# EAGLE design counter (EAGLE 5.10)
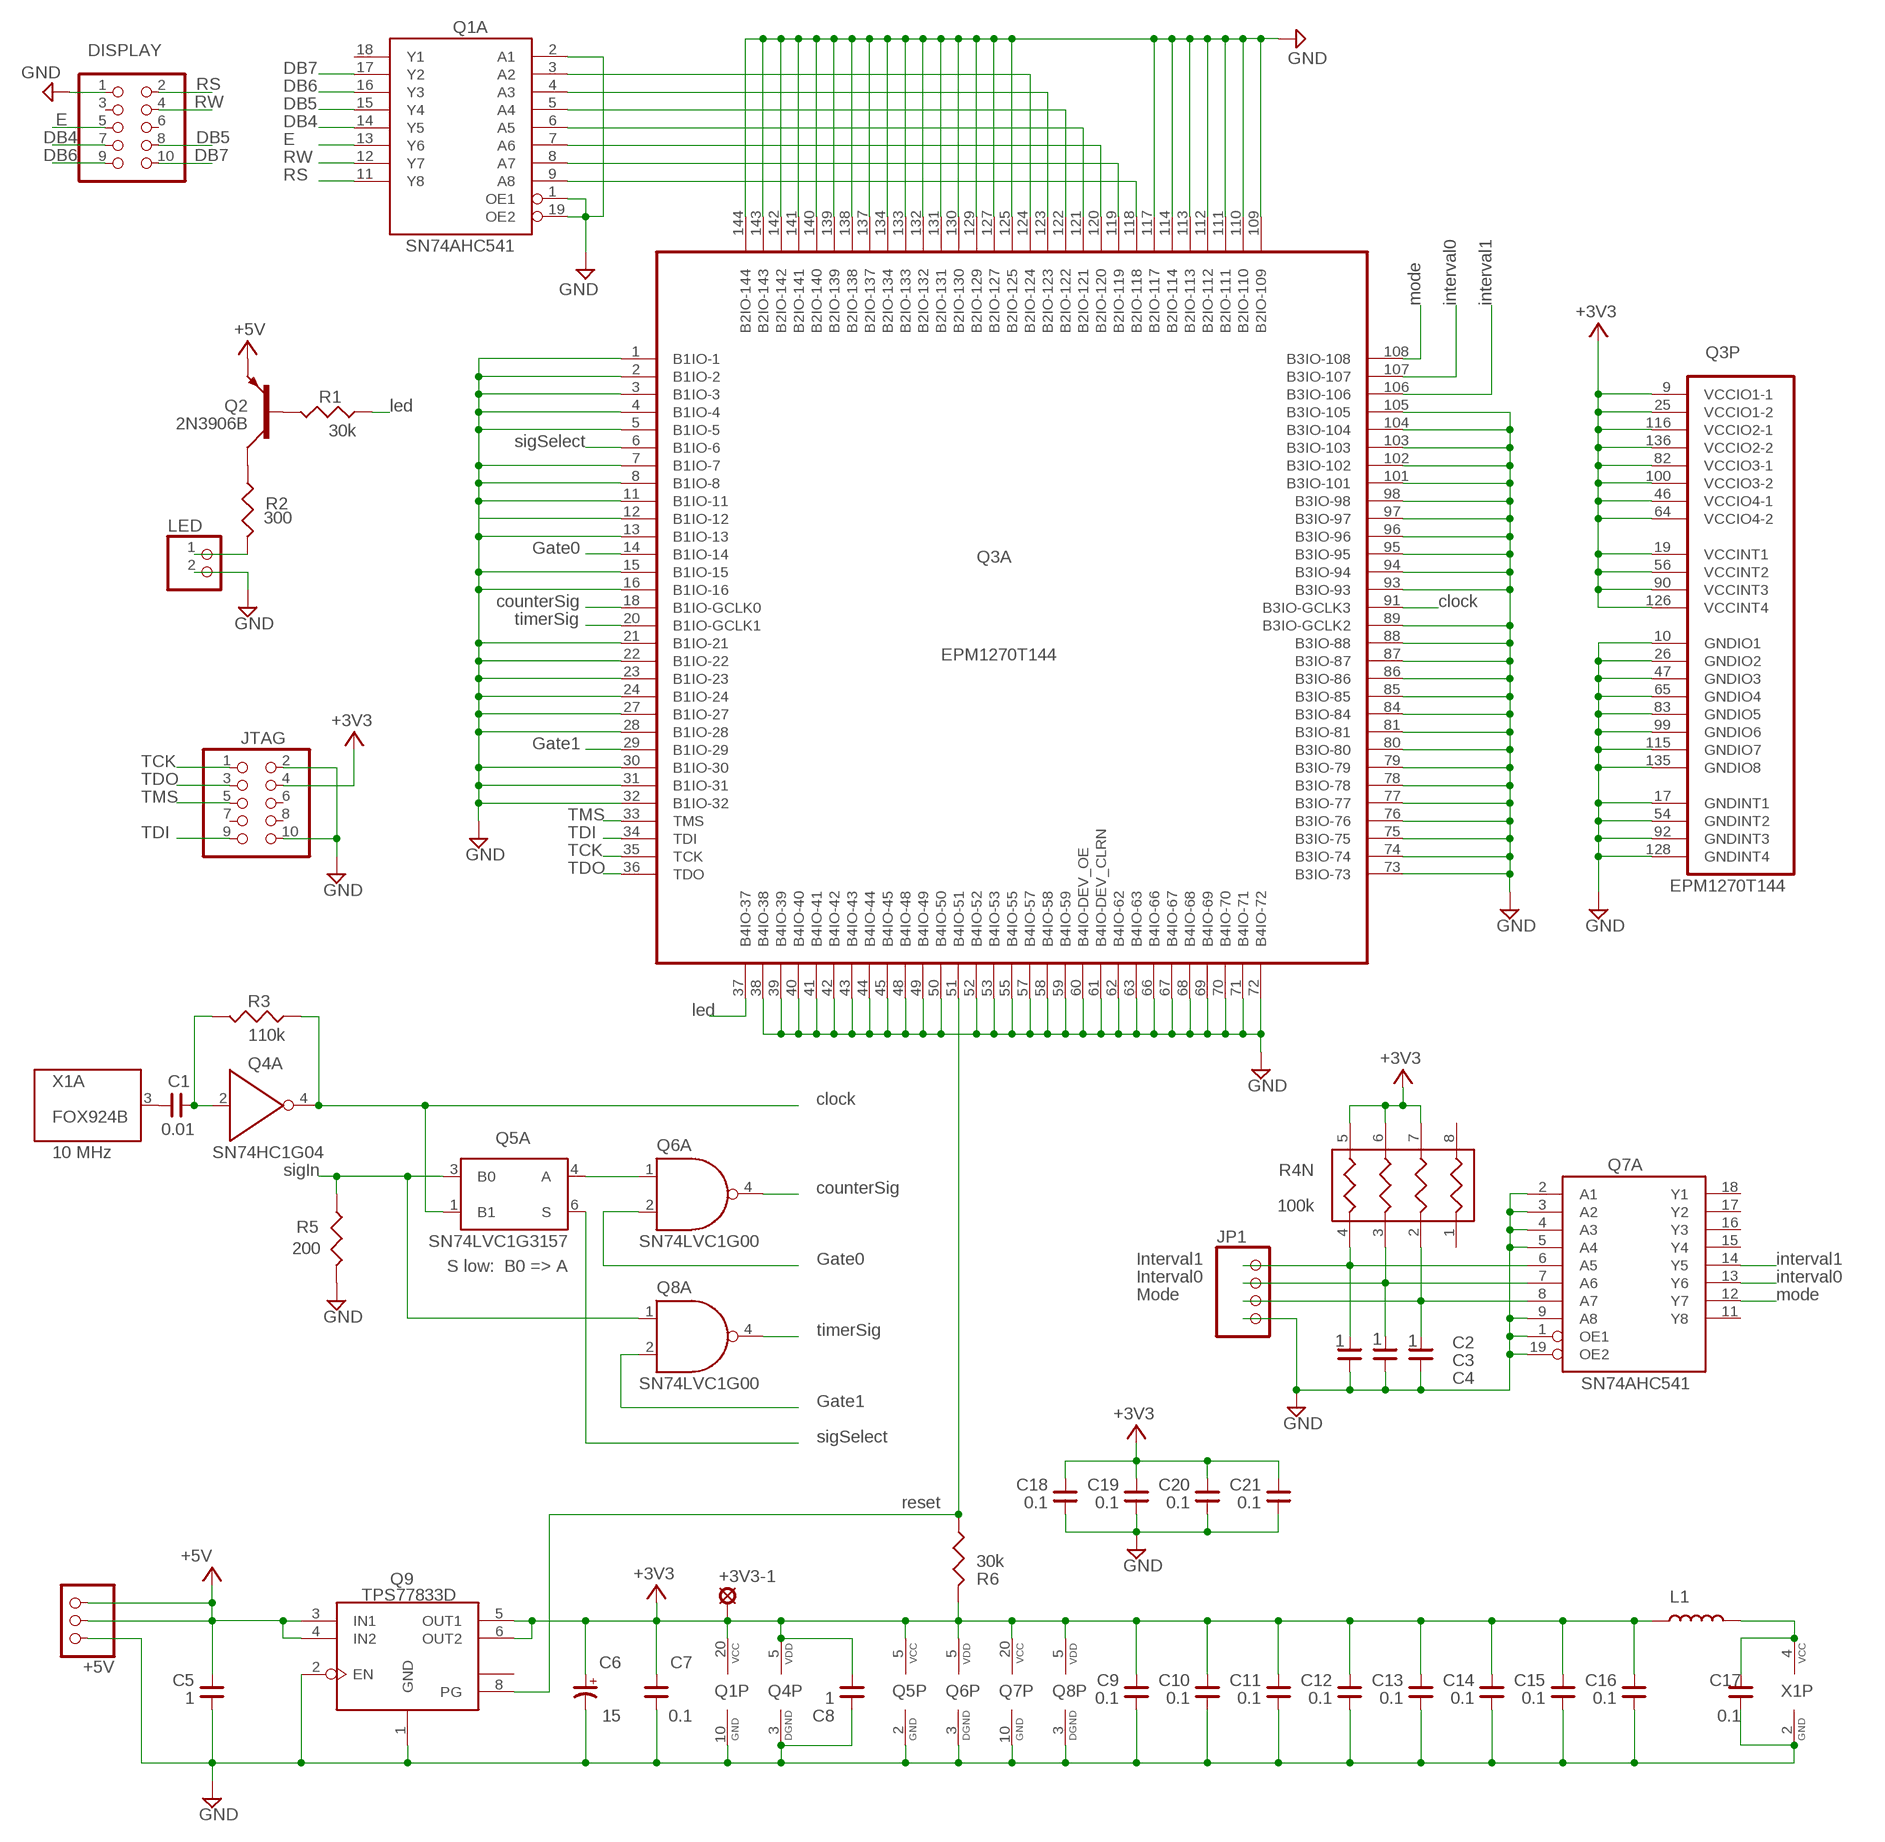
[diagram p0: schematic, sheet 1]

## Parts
+3V3-1  LSP10  [LSP10]
+5V  PINHD-1X3A  [1X03A]
C1  0.01  CAP-NPDC  [805C]
C2  1  CAP-NPDC  [805C]
C3  1  CAP-NPDC  [805C]
C4  1  CAP-NPDC  [805C]
C5  1  CAP-NPDC  [805C]
C6  15  CAP-PH  [BC45196H-B]
C7  0.1  CAP-NPDC  [805C]
C8  1  CAP-NPDC  [805C]
C9  0.1  CAP-NPDC  [805C]
C10  0.1  CAP-NPDC  [805C]
C11  0.1  CAP-NPDC  [805C]
C12  0.1  CAP-NPDC  [805C]
C13  0.1  CAP-NPDC  [805C]
C14  0.1  CAP-NPDC  [805C]
C15  0.1  CAP-NPDC  [805C]
C16  0.1  CAP-NPDC  [805C]
C17  0.1  CAP-NPDC  [805C]
C18  0.1  CAP-NPDC  [805C]
C19  0.1  CAP-NPDC  [805C]
C20  0.1  CAP-NPDC  [805C]
C21  0.1  CAP-NPDC  [805C]
DISPLAY  FOUR-WALL-2X5  [4W-2X5]
JP1  PINHD-1X4A  [1X4A-A]
JTAG  FOUR-WALL-2X5  [4W-2X5]
L1  INDUCTORC  [805A]
LED  PINHD-1X2  [1X02]
Q1  SN74AHC541  [TSSOP20]
Q2  2N3906B  [SOT23-3]
Q3  EPM1270T144  EPM1270T144-2  [TQFP144]
Q4  SN74HC1G04  1G04  [SOT-23-5]
Q5  SN74LVC1G3157  FSA3157A  [SOT-23-6]
Q6  SN74LVC1G00  1G00  [SOT23-5]
Q7  SN74AHC541  [TSSOP20]
Q8  SN74LVC1G00  1G00  [SOT23-5]
Q9  TPS77833D  [SOIC8]
R1  30k  RESISTORC  [805C]
R2  300  RESISTORC  [805C]
R3  110k  RESISTORC  [805C]
R4N  100k  RESISTOR-4-ARRAY  [1206-4-ARRAY]
R5  200  RESISTORC  [805C]
R6  30k  RESISTORC  [805C]
X1  FOX924B  OSC-NO-ENABLE  [FOX924]

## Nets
+3V3: +3V3-1.MP C6.+ C7.2 C8.2 C9.2 C10.2 C11.2 C12.2 C13.2 C14.2 C15.2 C16.2 C18.2 C19.2 C20.2 C21.2 JTAG.4 L1.1 Q1.20(P:VCC) Q3.9(P:VCCIO1-1) Q3.19(P:VCCINT1) Q3.25(P:VCCIO1-2) Q3.46(P:VCCIO4-1) Q3.56(P:VCCINT2) Q3.64(P:VCCIO4-2) Q3.82(P:VCCIO3-1) Q3.90(P:VCCINT3) Q3.100(P:VCCIO3-2) Q3.116(P:VCCIO2-1) Q3.126(P:VCCINT4) Q3.136(P:VCCIO2-2) Q4.5(P:VDD) Q5.5(P:VCC) Q6.5(P:VDD) Q7.20(P:VCC) Q8.5(P:VDD) Q9.5(OUT1) Q9.6(OUT2) R4N.5 R4N.6 R4N.7 R6.2
+5V: +5V.2 +5V.3 C5.2 Q2.2(E) Q9.3(IN1) Q9.4(IN2)
CLOCK: Q3.91(A:B3IO-GCLK3) Q4.4(A:Q) Q5.1(A:B1) R3.1
COUNTERSIG: Q3.18(A:B1IO-GCLK0) Q6.4(A:Y)
DB4: DISPLAY.7 Q1.14(A:Y5)
DB5: DISPLAY.8 Q1.15(A:Y4)
DB6: DISPLAY.9 Q1.16(A:Y3)
DB7: DISPLAY.10 Q1.17(A:Y2)
E: DISPLAY.5 Q1.13(A:Y6)
GATE0: Q3.14(A:B1IO-14) Q6.2(A:B)
GATE1: Q3.29(A:B1IO-29) Q8.2(A:B)
GND: +5V.1 C2.1 C3.1 C4.1 C5.1 C6.- C7.1 C8.1 C9.1 C10.1 C11.1 C12.1 C13.1 C14.1 C15.1 C16.1 C17.1 C18.1 C19.1 C20.1 C21.1 DISPLAY.1 JP1.4 JTAG.2 JTAG.10 LED.2 Q1.1(A:OE1) Q1.2(A:A1) Q1.10(P:GND) Q1.19(A:OE2) Q3.1(A:B1IO-1) Q3.2(A:B1IO-2) Q3.3(A:B1IO-3) Q3.4(A:B1IO-4) Q3.5(A:B1IO-5) Q3.7(A:B1IO-7) Q3.8(A:B1IO-8) Q3.10(P:GNDIO1) Q3.11(A:B1IO-11) Q3.12(A:B1IO-12) Q3.13(A:B1IO-13) Q3.15(A:B1IO-15) Q3.16(A:B1IO-16) Q3.17(P:GNDINT1) Q3.21(A:B1IO-21) Q3.22(A:B1IO-22) Q3.23(A:B1IO-23) Q3.24(A:B1IO-24) Q3.26(P:GNDIO2) Q3.27(A:B1IO-27) Q3.28(A:B1IO-28) Q3.30(A:B1IO-30) Q3.31(A:B1IO-31) Q3.32(A:B1IO-32) Q3.38(A:B4IO-38) Q3.39(A:B4IO-39) Q3.40(A:B4IO-40) Q3.41(A:B4IO-41) Q3.42(A:B4IO-42) Q3.43(A:B4IO-43) Q3.44(A:B4IO-44) Q3.45(A:B4IO-45) Q3.47(P:GNDIO3) Q3.48(A:B4IO-48) Q3.49(A:B4IO-49) Q3.50(A:B4IO-50) Q3.52(A:B4IO-52) Q3.53(A:B4IO-53) Q3.54(P:GNDINT2) Q3.55(A:B4IO-55) Q3.57(A:B4IO-57) Q3.58(A:B4IO-58) Q3.59(A:B4IO-59) Q3.60(A:B4IO-DEV_OE) Q3.61(A:B4IO-DEV_CLRN) Q3.62(A:B4IO-62) Q3.63(A:B4IO-63) Q3.65(P:GNDIO4) Q3.66(A:B4IO-66) Q3.67(A:B4IO-67) Q3.68(A:B4IO-68) Q3.69(A:B4IO-69) Q3.70(A:B4IO-70) Q3.71(A:B4IO-71) Q3.72(A:B4IO-72) Q3.73(A:B3IO-73) Q3.74(A:B3IO-74) Q3.75(A:B3IO-75) Q3.76(A:B3IO-76) Q3.77(A:B3IO-77) Q3.78(A:B3IO-78) Q3.79(A:B3IO-79) Q3.80(A:B3IO-80) Q3.81(A:B3IO-81) Q3.83(P:GNDIO5) Q3.84(A:B3IO-84) Q3.85(A:B3IO-85) Q3.86(A:B3IO-86) Q3.87(A:B3IO-87) Q3.88(A:B3IO-88) Q3.89(A:B3IO-GCLK2) Q3.92(P:GNDINT3) Q3.93(A:B3IO-93) Q3.94(A:B3IO-94) Q3.95(A:B3IO-95) Q3.96(A:B3IO-96) Q3.97(A:B3IO-97) Q3.98(A:B3IO-98) Q3.99(P:GNDIO6) Q3.101(A:B3IO-101) Q3.102(A:B3IO-102) Q3.103(A:B3IO-103) Q3.104(A:B3IO-104) Q3.105(A:B3IO-105) Q3.109(A:B2IO-109) Q3.110(A:B2IO-110) Q3.111(A:B2IO-111) Q3.112(A:B2IO-112) Q3.113(A:B2IO-113) Q3.114(A:B2IO-114) Q3.115(P:GNDIO7) Q3.117(A:B2IO-117) Q3.125(A:B2IO-125) Q3.127(A:B2IO-127) Q3.128(P:GNDINT4) Q3.129(A:B2IO-129) Q3.130(A:B2IO-130) Q3.131(A:B2IO-131) Q3.132(A:B2IO-132) Q3.133(A:B2IO-133) Q3.134(A:B2IO-134) Q3.135(P:GNDIO8) Q3.137(A:B2IO-137) Q3.138(A:B2IO-138) Q3.139(A:B2IO-139) Q3.140(A:B2IO-140) Q3.141(A:B2IO-141) Q3.142(A:B2IO-142) Q3.143(A:B2IO-143) Q3.144(A:B2IO-144) Q4.3(P:DGND) Q5.2(P:GND) Q6.3(P:DGND) Q7.1(A:OE1) Q7.2(A:A1) Q7.3(A:A2) Q7.4(A:A3) Q7.5(A:A4) Q7.9(A:A8) Q7.10(P:GND) Q7.19(A:OE2) Q8.3(P:DGND) Q9.1(GND) Q9.2(EN) R5.2 X1.2(P:GND)
INTERVAL0: Q3.107(A:B3IO-107) Q7.13(A:Y6)
INTERVAL0I: C3.2 JP1.2 Q7.7(A:A6) R4N.3
INTERVAL1: Q3.106(A:B3IO-106) Q7.14(A:Y5)
INTERVAL1I: C4.2 JP1.3 Q7.8(A:A7) R4N.2
LED: Q3.37(A:B4IO-37) R1.1
MODE: Q3.108(A:B3IO-108) Q7.12(A:Y7)
MODEI: C2.2 JP1.1 Q7.6(A:A5) R4N.4
N$1: Q1.3(A:A2) Q3.124(A:B2IO-124)
N$8: C1.2 X1.3(A:OUT)
N$13: C1.1 Q4.2(A:A) R3.2
N$14: Q1.4(A:A3) Q3.123(A:B2IO-123)
N$16: Q5.4(A:A) Q6.1(A:A)
N$17: Q1.5(A:A4) Q3.122(A:B2IO-122)
N$18: Q1.6(A:A5) Q3.121(A:B2IO-121)
N$19: Q1.7(A:A6) Q3.120(A:B2IO-120)
N$20: Q2.3(C) R2.1
N$21: LED.1 R2.2
N$22: Q1.8(A:A7) Q3.119(A:B2IO-119)
N$23: Q1.9(A:A8) Q3.118(A:B2IO-118)
N$25: Q2.1(B) R1.2
N$27: C17.2 L1.2 X1.4(P:VCC)
RESET: Q3.51(A:B4IO-51) Q9.8(PG) R6.1
RS: DISPLAY.2 Q1.11(A:Y8)
RW: DISPLAY.4 Q1.12(A:Y7)
SIGIN: Q5.3(A:B0) Q8.1(A:A) R5.1
SIGSELECT: Q3.6(A:B1IO-6) Q5.6(A:S)
TCK: JTAG.1 Q3.35(A:TCK)
TDI: JTAG.9 Q3.34(A:TDI)
TDO: JTAG.3 Q3.36(A:TDO)
TIMERSIG: Q3.20(A:B1IO-GCLK1) Q8.4(A:Y)
TMS: JTAG.5 Q3.33(A:TMS)
Unconnected: DISPLAY.3 DISPLAY.6 JTAG.6 JTAG.7 JTAG.8 Q1.18(A:Y1) Q7.11(A:Y8) Q7.15(A:Y4) Q7.16(A:Y3) Q7.17(A:Y2) Q7.18(A:Y1) Q9.7(NC) R4N.1 R4N.8

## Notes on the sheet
- DB7
- RS | DB6
- RW | DB5
- E | DB4
- DB4 | DB5 | E
- DB6 | DB7 | RW
- RS
- mode | interval0 | interval1
- led
- sigSelect
- Gate0
- counterSig | clock
- timerSig
- Gate1
- TCK
- TDO
- TMS
- TMS
- TDI | TDI
- TCK
- TDO
- led
- clock
- 10 MHz
- sigIn
- counterSig
- Gate0 | Interval1 | interval1
- S low:  B0 => A
- Interval0 | interval0
- Mode | mode
- timerSig
- Gate1
- sigSelect
- reset

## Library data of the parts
+3V3-1 = agar2:LSP10: SOLDER PAD
+5V = agarConn:PINHD-1X3
C1-C5 C7-C21 = agar:CAP-NP: Non-polarized capacitor
C6 = agar:CAP-P: Polarized capacitor
DISPLAY JTAG = agarConn:FOUR-WALL-2X5
JP1 = agarConn:PINHD-1X4
L1 = agar:INDUCTOR: Fixed inductor
LED = agarConn:PINHD-1X2: PIN HEADER
Q1 Q7 = agarDigital:SN74AHC541: Octal buffer/driver with 3-state outputs
Q2 = agar:2N3906: PNP TRANSISTOR
Q3 = epm1270t144:EPM1270T144-2: EMP1270T144
Q4 = agarDigital:1G04: NOT
Q5 = agarDigital:FSA3157: Low-voltage SPDT analog switch
Q6 Q8 = agarDigital:1G00: Single positive-nand gate
Q9 = agarVoltageReg:TPS77833D: LDO reg with power-good output.
R1-R3 R5 R6 = agar:RESISTOR
R4N = agar:RESISTOR-4-ARRAY
X1 = agar:OSC-NO-ENABLE

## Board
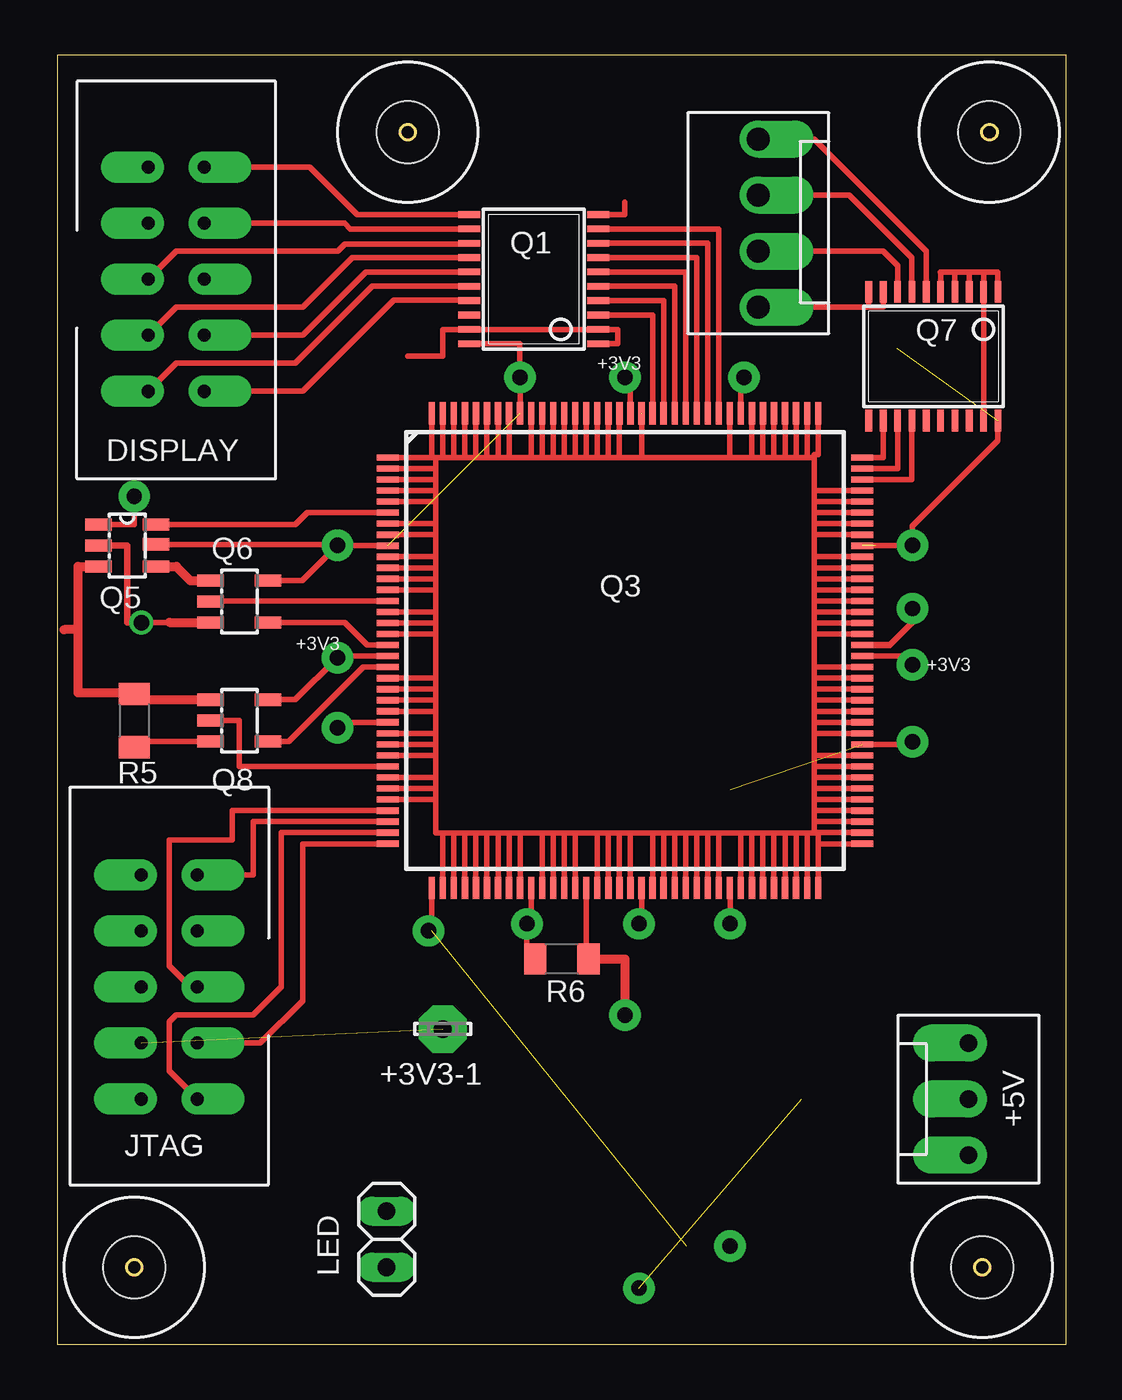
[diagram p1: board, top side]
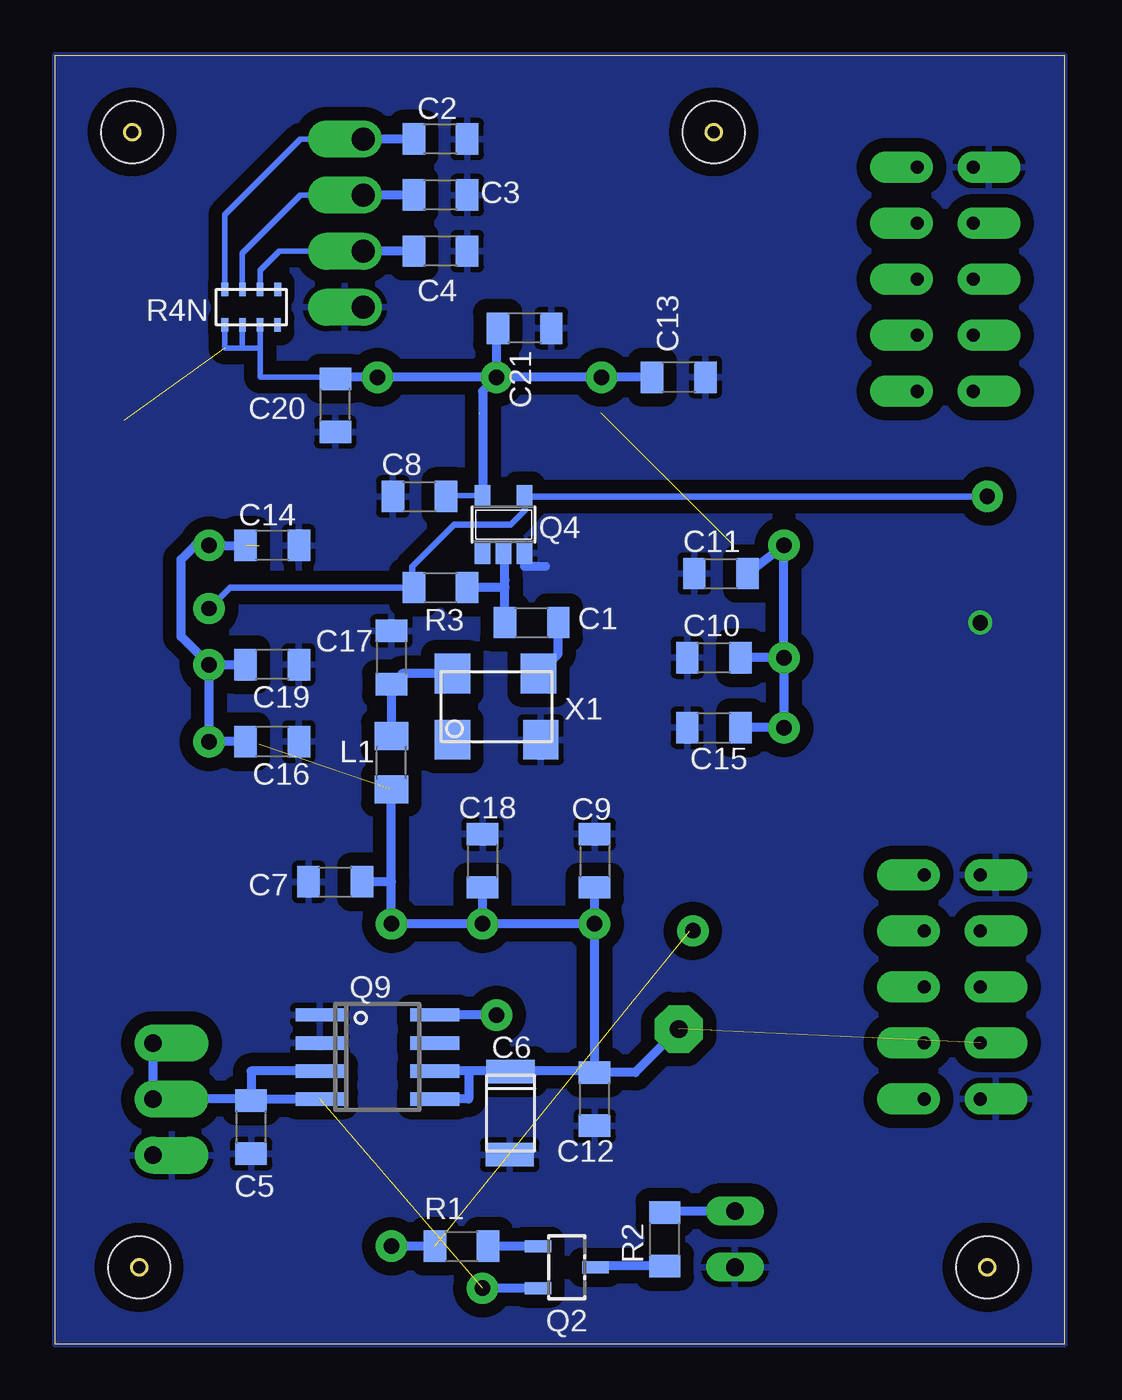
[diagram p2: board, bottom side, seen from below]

Size 45.71 x 58.41 mm. Coordinates in mm from the lower left corner, seen from the top.
Outline: 0,0 45.71,0 45.71,58.41 0,58.41 0,0
Copper layers (1*16): Top 0.035mm / dielectric 1.5mm / Bottom 0.035mm
Design rules "default *": minimum track width 10mil, minimum drill 24mil, track to track 8mil, track to pad 8mil, pad to pad 8mil, via to via 8mil, smd to smd 8mil, copper to edge 0mil, drill to drill 8mil, minimum pad ring 10mil, minimum via ring 8mil, stop-mask expansion 4mil, vias tented up to drill 0mil, thermal gap 10mil

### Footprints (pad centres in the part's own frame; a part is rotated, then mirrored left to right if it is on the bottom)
LSP10 = drill 0.8 pad 2.159 octagon: MP 0,0
1X03A = drill 0.8 pad 1.676 offset: 1 0,2.54; 2 0,0; 3 0,-2.54
805C = smd 1.016 x 1.422: 1 -1.206,0; 2 1.206,0
BC45196H-B = smd 1.067 x 2.184: + -1.883,0; - 1.883,-0.038
4W-2X5 = drill 0.6 pad 1.422 offset: 1 -5.08,-1.27; 2 -5.08,1.27; 3 -2.54,-1.27; 4 -2.54,1.27; 5 0,-1.27; 6 0,1.27; 7 2.54,-1.27; 8 2.54,1.27; 9 5.08,-1.27; 10 5.08,1.27
1X4A-A = drill 1.041 pad 1.676 offset: 1 0,3.81; 2 0,1.27; 3 0,-1.27; 4 0,-3.81
805A = smd 1.27 x 1.524: 1 -1.206,0; 2 1.206,0
1X02 = drill 0.8 long: 1 -1.27,0; 2 1.27,0
TSSOP20 = smd 0.305 x 0.991: 1 -2.925,-2.918; 2 -2.275,-2.918; 3 -1.625,-2.918; 4 -0.975,-2.918; 5 -0.325,-2.918; 6 0.325,-2.918; 7 0.975,-2.918; 8 1.625,-2.918; 9 2.275,-2.918; 10 2.925,-2.918; 11 2.925,2.918; 12 2.275,2.918; 13 1.625,2.918; 14 0.975,2.918; 15 0.325,2.918; 16 -0.325,2.918; 17 -0.975,2.918; 18 -1.625,2.918; 19 -2.275,2.918; 20 -2.925,2.918
SOT23-3 = smd 0.55 x 1.2: 1 0.95,1.3; 2 -0.95,1.3; 3 0,-1.3
TQFP144 = smd 1 x 0.279: 1 -10.75,8.75 | smd 1 x 0.282: 2 -10.75,8.25; 3 -10.75,7.75; 4 -10.75,7.25; 5 -10.75,6.75; 6 -10.75,6.25; 7 -10.75,5.75; 8 -10.75,5.25; 9 -10.75,4.75; 10 -10.75,4.25; 11 -10.75,3.75; 12 -10.75,3.25; 13 -10.75,2.75; 14 -10.75,2.25; 15 -10.75,1.75; 16 -10.75,1.25; 17 -10.75,0.75; 18 -10.75,0.25; 19 -10.75,-0.25; 20 -10.75,-0.75; 21 -10.75,-1.25; 22 -10.75,-1.75; 23 -10.75,-2.25; 24 -10.75,-2.75; 25 -10.75,-3.25; 26 -10.75,-3.75; 27 -10.75,-4.25; 28 -10.75,-4.75; 29 -10.75,-5.25; 30 -10.75,-5.75; 31 -10.75,-6.25; 32 -10.75,-6.75; 33 -10.75,-7.25; 34 -10.75,-7.75; 35 -10.75,-8.25; 36 -10.75,-8.75; 73 10.75,-8.75; 74 10.75,-8.25; 75 10.75,-7.75; 76 10.75,-7.25; 77 10.75,-6.75; 78 10.75,-6.25; 79 10.75,-5.75; 80 10.75,-5.25; 81 10.75,-4.75; 82 10.75,-4.25; 83 10.75,-3.75; 84 10.75,-3.25; 85 10.75,-2.75; 86 10.75,-2.25; 87 10.75,-1.75; 88 10.75,-1.25; 89 10.75,-0.75; 90 10.75,-0.25; 91 10.75,0.25; 92 10.75,0.75; 93 10.75,1.25; 94 10.75,1.75; 95 10.75,2.25; 96 10.75,2.75; 97 10.75,3.25; 98 10.75,3.75; 99 10.75,4.25; 100 10.75,4.75; 101 10.75,5.25; 102 10.75,5.75; 103 10.75,6.25; 104 10.75,6.75; 105 10.75,7.25; 106 10.75,7.75; 107 10.75,8.25; 108 10.75,8.75 | smd 0.282 x 1: 37 -8.75,-10.75; 38 -8.25,-10.75; 39 -7.75,-10.75; 40 -7.25,-10.75; 41 -6.75,-10.75; 42 -6.25,-10.75; 43 -5.75,-10.75; 44 -5.25,-10.75; 46 -4.25,-10.75; 47 -3.75,-10.75; 48 -3.25,-10.75; 49 -2.75,-10.75; 50 -2.25,-10.75; 51 -1.75,-10.75; 52 -1.25,-10.75; 53 -0.75,-10.75; 54 -0.25,-10.75; 55 0.25,-10.75; 56 0.75,-10.75; 57 1.25,-10.75; 58 1.75,-10.75; 59 2.25,-10.75; 60 2.75,-10.75; 61 3.25,-10.75; 62 3.75,-10.75; 63 4.25,-10.75; 64 4.75,-10.75; 65 5.25,-10.75; 66 5.75,-10.75; 67 6.25,-10.75; 68 6.75,-10.75; 69 7.25,-10.75; 70 7.75,-10.75; 71 8.25,-10.75; 72 8.75,-10.75; 109 8.75,10.75; 110 8.25,10.75; 111 7.75,10.75; 112 7.25,10.75; 113 6.75,10.75; 114 6.25,10.75; 115 5.75,10.75; 116 5.25,10.75; 117 4.75,10.75; 118 4.25,10.75; 119 3.75,10.75; 120 3.25,10.75; 121 2.75,10.75; 122 2.25,10.75; 123 1.75,10.75; 124 1.25,10.75; 125 0.75,10.75; 126 0.25,10.75; 127 -0.25,10.75; 128 -0.75,10.75; 129 -1.25,10.75; 130 -1.75,10.75; 131 -2.25,10.75; 132 -2.75,10.75; 133 -3.25,10.75; 134 -3.75,10.75; 135 -4.25,10.75; 136 -4.75,10.75; 137 -5.25,10.75; 138 -5.75,10.75; 139 -6.25,10.75; 140 -6.75,10.75; 141 -7.25,10.75; 142 -7.75,10.75; 143 -8.25,10.75; 144 -8.75,10.75 | smd 0.3 x 1: 45 -4.75,-10.75
SOT-23-5 = smd 0.69 x 0.99: 1 -0.95,-1.29; 2 0,-1.29; 3 0.95,-1.29; 4 0.95,1.3; 5 -0.95,1.3
SOT-23-6 = smd 0.55 x 1.2: 1 -0.95,-1.3; 2 0,-1.3; 3 0.95,-1.3; 4 0.95,1.3; 5 -0.05,1.3; 6 -0.95,1.3
SOT23-5 = smd 0.55 x 1.2: 1 -0.95,-1.3; 2 0,-1.3; 3 0.95,-1.3; 4 0.95,1.3; 5 -0.95,1.3
SOIC8 = smd 0.6 x 2.2: 1 -1.905,-2.6; 2 -0.635,-2.6; 3 0.635,-2.6; 4 1.905,-2.6; 5 1.905,2.6; 6 0.635,2.6; 7 -0.635,2.6; 8 -1.905,2.6
1206-4-ARRAY = smd 0.305 x 0.61: 1 -1.2,-0.8; 2 -0.4,-0.8; 3 0.4,-0.8; 4 1.2,-0.8; 5 1.2,0.8; 6 0.4,0.8; 7 -0.4,0.8; 8 -1.194,0.808
MOUNTING-HOLE-PLAIN = hole 2.8: 0,0
FOX924 = smd 1.6 x 1.8: 1 -2,-1.5; 2 2,-1.5; 3 1.9,1.5; 4 -2,1.5

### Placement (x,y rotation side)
+3V3-1  17.46,14.29 0 top
+5V  41.27,11.11 180 top
C1  24.13,32.7 0 bottom
C2  28.26,54.61 180 bottom
C3  28.26,52.07 180 bottom
C4  28.26,49.53 180 bottom
C5  36.83,9.84 90 bottom
C6  25.08,10.48 270 bottom
C7  33.02,20.95 0 bottom
C8  29.21,38.42 0 bottom
C9  21.27,21.91 270 bottom
C10  15.88,31.11 0 bottom
C11  15.56,34.92 0 bottom
C12  21.27,11.11 90 bottom
C13  17.46,43.81 180 bottom
C14  35.88,36.2 180 bottom
C15  15.88,27.94 0 bottom
C16  35.88,27.3 180 bottom
C17  30.48,31.11 270 bottom
C18  26.35,21.91 270 bottom
C19  35.88,30.8 180 bottom
C20  33.02,42.55 90 bottom
C21  24.45,46.04 180 bottom
DISPLAY  5.4,48.26 270 top
JP1  31.75,50.8 0 top
JTAG  5.08,16.19 90 top
L1  30.48,26.35 90 bottom
LED  14.92,4.76 270 top
Q1  21.59,48.26 90 top
Q2  22.54,3.49 90 bottom
Q3  25.72,31.43 0 top
Q4  25.4,37.15 0 bottom
Q5  3.17,36.2 270 top
Q6  8.26,33.66 270 top
Q7  39.69,44.77 180 top
Q8  8.26,28.26 270 top
Q9  31.11,13.02 270 bottom
R1  27.3,4.45 0 bottom
R2  18.1,4.76 90 bottom
R3  28.26,34.29 0 bottom
R4N  36.83,46.99 180 bottom
R5  3.49,28.26 270 top
R6  22.86,17.46 180 top
U$1  [MOUNTING-HOLE-PLAIN]  3.49,3.49 0 top
U$2  [MOUNTING-HOLE-PLAIN]  41.91,3.49 0 top
U$3  [MOUNTING-HOLE-PLAIN]  42.23,54.93 0 top
U$4  [MOUNTING-HOLE-PLAIN]  15.88,54.93 0 top
X1  25.72,28.89 0 bottom

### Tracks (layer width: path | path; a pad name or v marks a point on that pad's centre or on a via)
+3V3  (via drill 0.7 pad 1.42)  (5 unrouted)
  Top 0.254: Q6.5 11.11,34.6 12.69,36.18 12.71,36.18 | 12.71,36.18 Q3.9 | 12.71,36.18 v12.7,36.2 12.65,36.24 Q5.5 | Q3.19 12.77,31.18 v12.7,31.11 10.79,29.21 Q8.5 | Q3.90 38.48,31.18 v38.73,30.8 | Q3.136 20.97,43.8 v20.95,43.81 20.95,45.34 Q1.20 | Q3.126 25.97,43.56 v25.72,43.81 | Q3.116 30.97,43.67 v31.11,43.81 | v30.48,19.05 Q3.64 | Q3.56 26.47,19.16 v26.35,19.05 | Q3.46 21.47,19.25 v21.27,19.05 21.27,17.46 R6.2 | Q3.25 12.94,28.18 v12.7,27.94 | Q7.20 42.61,40.96 38.73,37.08 v38.73,36.2 38.72,36.18 Q3.100 | Q3.82 38.61,27.18 v38.73,27.3
  Bottom 0.254: Q4.5 27.97,38.45 C8.2 | L1.1 30.42,25.08 | 33.02,43.81 36.43,43.81 36.43,45.14 | 36.43,45.14 R4N.7 | 36.43,45.14 37.23,45.14 | R4N.5 38.03,45.14 37.23,45.14 | 37.23,45.14 R4N.6
  Bottom 0.406: Q4.5 26.35,43.18 v25.72,43.81 | 30.48,20.95 v30.48,19.05 v26.35,19.05 | 30.48,20.95 L1.1 | v21.27,19.05 v26.35,19.05 | v38.73,30.8 v38.73,27.3 C16.2 | v38.73,30.8 40.01,32.07 40.01,35.56 39.37,36.2 C14.2 | v25.72,43.81 v20.95,43.81 C13.2 | v12.7,31.11 v12.7,36.2 C11.2 | v12.7,31.11 v12.7,27.94 C15.2 | v12.7,31.11 C10.2 | v21.27,19.05 C9.2 | v38.73,30.8 C19.2 | v26.35,19.05 C18.2 | 30.48,20.95 C7.2 | 25.08,12.38 26.99,12.38 | 26.99,12.38 Q9.6 | 25.08,12.38 C6.+ | Q9.5 26.99,11.11 26.99,12.38 | 25.08,12.38 21.91,12.38 C12.2 | C12.2 v21.27,19.05 | C12.2 19.43,12.32 +3V3-1.MP | C21.2 25.72,46.04 v25.72,43.81 | v25.72,43.81 v31.11,43.81 33.02,43.81 C20.2
+5V  (via drill 0.7 pad 1.42)  (1 unrouted)
  Bottom 0.406: +5V.3 +5V.2 36.83,11.11 | 36.83,11.11 Q9.4 | 36.83,11.11 C5.2 36.83,12.38 Q9.3 | Q2.2 v26.35,2.54
CLOCK  (via drill 0.7 pad 1.42)
  Top 0.254: Q5.1 3.49,37.15 v3.49,38.42
  Top 0.305: Q3.91 37.72,31.68 38.73,32.7 v38.73,33.34
  Bottom 0.254: v3.49,38.42 3.49,38.35 | 29.53,34.35 R3.1 | 24.45,38.42 Q4.4
  Bottom 0.305: Q4.4 24.45,37.78 25.08,37.15 27.62,37.15 29.53,35.24 29.53,34.35 | v3.49,38.42 24.45,38.42 | R3.1 37.78,34.29 v38.73,33.34
COUNTERSIG
  Top 0.254: Q3.18 14.04,31.68 13.02,32.7 Q6.4
DB4
  Top 0.254: Q1.14 13.36,49.23 11.11,46.99 5.4,46.99 DISPLAY.7
DB5
  Top 0.254: Q1.15 18.66,48.58 13.97,48.58 11.11,45.72 DISPLAY.8
DB6
  Top 0.254: Q1.16 14.28,47.94 10.79,44.45 5.4,44.45 DISPLAY.9
DB7
  Top 0.254: Q1.17 18.65,47.31 15.24,47.31 11.11,43.18 DISPLAY.10
E
  Top 0.254: Q1.13 18.64,49.85 13.02,49.85 12.7,49.53 5.4,49.53 DISPLAY.5
GATE0
  Top 0.254: Q3.14 6.96,33.68 Q6.2
GATE1
  Top 0.254: Q8.2 8.26,28.26 8.26,26.18 Q3.29
GND  (via drill 0.7)  (1 unrouted)
  Top 0.254: v3.81,32.7 5.08,32.7 | Q8.3 3.75,27.31 R5.2 | 15.88,44.77 17.46,44.77 17.46,45.98 Q1.19 Q1.2 25.4,45.98 25.4,45.34 Q1.1 | 17.14,40.18 16.97,40.18 | 17.14,26.68 17.14,27.18 | 17.14,24.68 17.14,23.18 17.46,23.18 | 17.14,39.68 17.14,40.18 | 18.47,23.18 18.97,23.18 | 19.47,23.18 19.97,23.18 | 21.97,23.18 22.47,23.18 | 22.97,23.18 23.47,23.18 | 24.47,23.18 24.97,23.18 | 25.47,23.18 25.97,23.18 | 32.47,23.18 32.97,23.18 | 31.47,23.18 31.97,23.18 | 28.97,23.18 29.47,23.18 | 27.97,23.18 28.47,23.18 | 18.47,40.18 18.97,40.18 | 19.97,40.18 20.47,40.18 | 22.47,40.18 22.97,40.18 | 24.97,40.18 25.47,40.18 | 34.29,38.68 34.29,38.18 | 34.29,37.68 34.29,37.18 | 34.29,33.68 34.29,34.18 | 34.29,32.18 34.29,32.68 | 34.29,30.18 34.29,30.68 | 34.29,28.68 34.29,29.18 | 34.29,27.68 34.29,28.18 | 34.29,25.18 34.29,25.68 | 34.29,23.18 34.29,23.68 | 17.14,39.68 Q3.2 | 17.14,39.18 17.14,39.68 | 17.14,39.18 Q3.3 | 17.14,38.68 17.14,39.18 | 17.14,38.68 Q3.4 | 17.14,38.18 17.14,38.68 | 17.14,38.18 Q3.5 | 17.14,37.18 17.14,38.18 | 17.14,37.18 Q3.7 | 17.14,36.68 17.14,37.18 | 17.14,36.68 Q3.8 | 17.14,33.18 Q3.15 | 17.14,32.68 17.14,33.18 | 17.14,32.68 Q3.16 | 17.14,32.18 17.14,32.68 | 17.14,32.18 Q3.17 | 17.14,30.18 17.14,32.18 | 17.14,30.18 Q3.21 | 17.14,29.68 17.14,30.18 | 17.14,29.68 Q3.22 | 17.14,29.18 17.14,29.68 | 17.14,29.18 Q3.23 | 17.14,28.68 17.14,29.18 | 17.14,28.68 Q3.24 | 17.14,27.68 17.14,28.68 | 17.14,27.68 Q3.26 | 17.14,27.18 Q3.27 | 17.14,27.18 17.14,27.68 | 17.14,26.68 Q3.28 | 17.14,25.68 Q3.30 | 17.14,25.68 17.14,26.68 | Q3.31 17.14,25.18 | 17.14,25.18 17.14,25.68 | 17.14,24.68 Q3.32 | 17.14,25.18 17.14,24.68 | Q3.38 17.46,23.18 | 17.46,23.18 17.97,23.18 | 17.97,23.18 Q3.39 | 17.97,23.18 18.47,23.18
  Top 0.254: 18.47,23.18 Q3.40 | 18.97,23.18 Q3.41 | 18.97,23.18 19.47,23.18 | 19.47,23.18 Q3.42 | 19.97,23.18 Q3.43 | 19.97,23.18 20.47,23.18 | 20.47,23.18 Q3.44 | 20.47,23.18 20.97,23.18 | 20.97,23.18 Q3.45 | 20.97,23.18 21.97,23.18 | 21.97,23.18 Q3.47 | 22.47,23.18 Q3.48 | 22.47,23.18 22.97,23.18 | 22.97,23.18 Q3.49 | 23.47,23.18 Q3.50 | 23.47,23.18 24.47,23.18 | 24.47,23.18 Q3.52 | 24.97,23.18 Q3.53 | 24.97,23.18 25.47,23.18 | 25.47,23.18 Q3.54 | 25.97,23.18 26.97,23.18 | 25.97,23.18 Q3.55 | 26.97,23.18 27.47,23.18 | 26.97,23.18 Q3.57 | 27.47,23.18 Q3.58 | 27.47,23.18 27.97,23.18 | 27.97,23.18 Q3.59 | 28.47,23.18 Q3.60 | 28.47,23.18 28.97,23.18 | 28.97,23.18 Q3.61 | 29.47,23.18 Q3.62 | 29.47,23.18 29.97,23.18 | 29.97,23.18 Q3.63 | 29.97,23.18 30.97,23.18 | 30.97,23.18 Q3.65 | 30.97,23.18 31.47,23.18 | 31.47,23.18 Q3.66 | 31.97,23.18 Q3.67 | 31.97,23.18 32.47,23.18 | 32.47,23.18 Q3.68 | 32.97,23.18 33.47,23.18 | 32.97,23.18 Q3.69 | 33.47,23.18 33.97,23.18 | 33.47,23.18 Q3.70 | 33.97,23.18 34.29,23.18 | 33.97,23.18 Q3.71 | 34.29,23.18 34.47,23.18 | 34.47,23.18 34.47,22.68 | Q3.74 34.47,23.18 | 34.47,22.68 Q3.73 | 34.47,22.68 Q3.72 | 34.29,23.68 Q3.75 | 34.29,24.18 Q3.76 | 34.29,23.68 34.29,24.18 | 34.29,24.68 Q3.77 | 34.29,24.18 34.29,24.68 | 34.29,25.18 Q3.78 | 34.29,24.68 34.29,25.18 | 34.29,25.68 Q3.79 | 34.29,26.18 Q3.80 | 34.29,25.68 34.29,26.18 | 34.29,26.68 Q3.81 | 34.29,26.18 34.29,26.68 | 34.29,27.68 Q3.83 | 34.29,26.68 34.29,27.68 | 34.29,28.18 Q3.84 | 34.29,28.68 Q3.85 | 34.29,28.18 34.29,28.68 | 34.29,29.18 Q3.86 | 34.29,29.18 34.29,29.68 | 34.29,29.68 Q3.87 | 34.29,30.18 Q3.88 | 34.29,29.68 34.29,30.18 | 34.29,30.68 Q3.89 | 34.29,32.18 Q3.92 | 34.29,30.68 34.29,32.18 | 34.29,32.68 Q3.93 | 34.29,32.68 34.29,33.18
  Top 0.254: 34.29,33.18 Q3.94 | 34.29,33.68 Q3.95 | 34.29,33.18 34.29,33.68 | 34.29,34.18 Q3.96 | 34.29,34.18 34.29,34.68 | 34.29,34.68 Q3.97 | 34.29,34.68 34.29,35.18 | 34.29,35.18 Q3.98 | 34.29,35.68 Q3.99 | 34.29,35.68 34.29,35.18 | 34.29,36.68 Q3.101 | 34.29,36.68 34.29,35.68 | 34.29,37.18 Q3.102 | 34.29,37.18 34.29,36.68 | 34.29,37.68 Q3.103 | 34.29,38.18 Q3.104 | 34.29,38.18 34.29,37.68 | 34.29,38.68 Q3.105 | 34.29,40.18 34.29,38.68 | 34.29,40.18 34.29,40.32 34.47,40.32 Q3.109 | 33.97,40.18 34.29,40.18 | 33.97,40.18 Q3.110 | 32.97,40.18 33.47,40.18 | 32.97,40.18 Q3.112 | 32.47,40.18 32.97,40.18 | 31.97,40.18 Q3.114 | 31.47,40.18 31.97,40.18 | 31.47,40.18 Q3.115 | 30.47,40.18 31.47,40.18 | 30.47,40.18 Q3.117 | 26.47,40.18 30.47,40.18 | 26.47,40.18 Q3.125 | 25.47,40.18 26.47,40.18 | 25.47,40.18 Q3.127 | 24.47,40.18 24.97,40.18 | 24.97,40.18 Q3.128 | 23.97,40.18 24.47,40.18 | 24.47,40.18 Q3.129 | 23.97,40.18 Q3.130 | 23.47,40.18 23.97,40.18 | 23.47,40.18 Q3.131 | 22.97,40.18 23.47,40.18 | 22.97,40.18 Q3.132 | 21.97,40.18 22.47,40.18 | 22.47,40.18 Q3.133 | 21.97,40.18 Q3.134 | 21.47,40.18 21.97,40.18 | 21.47,40.18 Q3.135 | 20.47,40.18 21.47,40.18 | 20.47,40.18 Q3.137 | 19.47,40.18 19.97,40.18 | 19.97,40.18 Q3.138 | 19.47,40.18 Q3.139 | 18.97,40.18 19.47,40.18 | 18.97,40.18 Q3.140 | 17.97,40.18 18.47,40.18 | 18.47,40.18 Q3.141 | 17.47,40.18 17.97,40.18 | 17.97,40.18 Q3.142 | 17.14,40.18 17.47,40.18 | 17.47,40.18 Q3.143 | 16.97,40.18 Q3.1 | 16.97,40.18 Q3.144 | Q7.5 40.01,48.57 40.01,48.58 40.66,48.58 | 41.96,48.58 42.61,48.58 Q7.1 | 40.66,48.58 Q7.4 | 41.31,48.58 40.66,48.58 | 41.31,48.58 Q7.3 | 41.96,48.58 41.31,48.58 | 41.96,48.58 Q7.2 Q7.19 | JP1.4 36.76,46.99 | 36.76,46.99 Q7.10 | 36.76,46.99 37.41,46.99 Q7.9
  Top 0.254: 17.14,35.68 17.14,36.68 | 31.97,40.18 32.47,40.18 | 32.47,40.18 Q3.113 | 33.47,40.18 33.97,40.18 | 33.47,40.18 Q3.111 | 17.14,35.18 Q3.11 | 17.14,33.18 17.14,34.18 | 17.14,34.68 17.14,35.18 | 17.14,35.68 Q3.10 | 17.14,35.18 17.14,35.68 | 17.14,34.68 Q3.12 | 17.14,34.18 Q3.13 | 17.14,34.18 17.14,34.68 | Q1.10 25.72,51.19 25.72,51.75
  Top 0.305: Q5.2 3.17,36.2 3.17,32.7 v3.81,32.7
  Top 0.406: 5.08,32.7 Q6.3
  Bottom 0.406: Q4.3 24.45,35.24 23.5,35.24
  pour Bottom (isolate 0.61): 0,0 45.71,0 45.71,58.41 0,58.41
INTERVAL0
  Top 0.254: Q3.107 38.06,39.68 Q7.13
INTERVAL0I
  Top 0.254: JP1.2 35.88,52.07 38.71,49.23 Q7.7
  Bottom 0.254: JP1.2 34.61,52.07 37.23,49.45 R4N.3
  Bottom 0.406: C3.2 JP1.2
INTERVAL1
  Top 0.254: Q3.106 38.71,39.18 Q7.14
INTERVAL1I
  Top 0.254: JP1.3 37.41,49.53 38.06,48.88 Q7.8
  Bottom 0.254: JP1.3 35.56,49.53 36.43,48.66 R4N.2
  Bottom 0.406: C4.2 JP1.3
LED  (via drill 0.7 pad 1.42)  (1 unrouted)
  Top 0.254: v16.83,18.73 16.97,18.73 Q3.37
  Bottom 0.406: R1.1 v30.48,4.45
MODE
  Top 0.254: Q3.108 37.41,40.18 Q7.12
MODEI
  Top 0.254: JP1.1 34.29,54.61 39.36,49.54 Q7.6
  Bottom 0.254: JP1.1 34.61,54.61 38.03,51.19 R4N.4
  Bottom 0.406: C2.2 JP1.1
N$1
  Top 0.254: Q1.3 26.97,46.63 Q3.124
N$8
  Bottom 0.406: C1.2 22.92,31.29 X1.3
N$13
  Bottom 0.254: Q4.2 25.46,35.79 25.34,35.79
  Bottom 0.406: C1.1 25.34,34.29 | 25.34,35.79 25.34,34.61 25.34,34.29 | 25.34,34.29 R3.2
N$14
  Top 0.254: Q1.4 27.47,47.28 Q3.123
N$16
  Top 0.406: Q5.4 5.39,35.24 6.04,34.6 Q6.1
N$17
  Top 0.254: Q1.5 27.97,47.94 Q3.122
N$18
  Top 0.254: Q1.6 28.47,48.59 Q3.121
N$19
  Top 0.254: Q1.7 28.97,49.23 Q3.120
N$20
  Bottom 0.406: R2.1 21.24,3.56 Q2.3
N$21
  Bottom 0.406: LED.1 18.1,6.03 R2.2
N$22
  Top 0.254: Q1.8 29.47,49.88 Q3.119
N$23
  Top 0.254: Q1.9 29.97,50.53 Q3.118
N$25
  Bottom 0.406: Q2.1 R1.2
N$27
  Bottom 0.254: 30,30.39 C17.2
  Bottom 0.406: X1.4 30,30.39 | C17.2 L1.2
RESET  (via drill 0.7 pad 1.42)
  Top 0.254: R6.1 23.97,17.46 Q3.51
  Top 0.406: R6.1 25.72,17.46 v25.72,14.92
  Bottom 0.406: v25.72,14.92 Q9.8
RS
  Top 0.254: Q1.11 13.59,51.19 11.43,53.34 DISPLAY.2
RW
  Top 0.254: Q1.12 13.28,50.53 13.02,50.8 DISPLAY.4
SIGIN
  Top 0.254: 3.75,29.21 R5.1 3.49,29.53
  Top 0.406: 3.75,29.21 Q8.1 | Q5.3 0.95,35.24 0.95,32.38 | 0.95,32.38 0.95,29.53 3.49,29.53 | 0.95,32.38 0.32,32.38
SIGSELECT
  Top 0.254: Q3.6 11.33,37.68 10.79,37.15 Q5.6
TCK
  Top 0.254: Q3.35 10.16,23.18 10.16,16.19 8.89,14.92 5.4,14.92 5.08,14.61 5.08,12.38 JTAG.1
TDI
  Top 0.254: Q3.34 8.89,23.68 8.89,21.27 JTAG.9
TDO
  Top 0.254: Q3.36 11.11,22.68 11.11,15.56 9.21,13.65 JTAG.3
TIMERSIG
  Top 0.254: Q3.20 13.86,30.68 10.48,27.31 Q8.4
TMS
  Top 0.254: Q3.33 7.94,24.18 7.94,22.86 5.08,22.86 5.08,17.14 6.03,16.19 JTAG.5

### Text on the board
tNames: +3V3 | +3V3 | +3V3
_tNames: Q1 | Q1 | Q1 | Q1 | Q7 | Q3 | DISPLAY | Q7 | Q7 | Q7 | Q6 | Q6 | Q6 | Q6 | Q3 | Q3 | Q3 | Q5 | Q5 | Q5 | Q5 | R5 | R5 | R5 | R5 | Q8 | Q8 | Q8 | Q8 | +3V3-1 | +3V3-1 | +3V3-1 | R6 | R6 | R6 | R6 | +3V3-1 | +5V | JTAG | +5V | LED | LED | LED | LED
_bNames: C2 | C2 | C2 | C2 | C3 | C3 | C3 | C3 | R4N | R4N | R4N | C4 | C4 | C4 | C4 | C21 | C21 | C21 | C21 | R4N | C20 | C20 | C20 | C20 | C13 | C13 | C13 | C13 | Q4 | Q4 | Q4 | C8 | C8 | C8 | C8 | C14 | C11 | C11 | C11 | C11 | Q4 | R3 | R3 | R3 | C14 | C14 | C14 | R3 | C10 | C10 | C10 | C10 | C1 | C1 | C1 | C1 | C17 | C17 | C17 | C17 | C19 | C19 | C19 | C19 | X1 | X1 | X1 | X1 | C15 | C15 | C15 | C15 | L1 | L1 | L1 | L1 | C16 | C16 | C16 | C16 | C9 | C7 | C9 | C9 | C9 | C18 | C18 | C18 | C18 | C7 | C7 | C7 | Q9 | C6 | C12 | C12 | C12 | Q9 | Q9 | Q9 | C6 | C6 | C6 | C5 | C5 | C5 | C12 | R1 | C5 | R2 | R2 | R2 | R2 | R1 | R1 | R1 | Q2 | Q2 | Q2 | Q2
_tValues: SN74AHC541 | SN74AHC541 | SN74AHC541 | SN74AHC541 | SN74AHC541 | SN74AHC541 | SN74AHC541 | SN74AHC541 | SN74LVC1G3157 | SN74LVC1G3157 | SN74LVC1G3157 | SN74LVC1G3157 | SN74LVC1G00 | SN74LVC1G00 | SN74LVC1G00 | SN74LVC1G00 | 200 | 200 | 200 | 200 | SN74LVC1G00 | SN74LVC1G00 | SN74LVC1G00 | SN74LVC1G00 | EPM1270T144 | EPM1270T144 | EPM1270T144 | EPM1270T144 | 30k | 30k | 30k | 30k | LSP10 | LSP10 | LSP10 | LSP10 | LED
_bValues: 1 | 1 | 1 | 1 | 1 | 1 | 1 | 1 | 1 | 1 | 1 | 1 | 100k | 0.1 | 0.1 | 0.1 | 0.1 | 100k | 100k | 100k | 0.1 | 0.1 | 0.1 | 0.1 | 0.1 | 0.1 | 0.1 | 0.1 | 0.1 | 0.1 | 0.1 | 0.1 | 1 | 1 | 1 | 1 | 0.1 | 0.1 | 0.1 | 0.1 | SN74HC1G04 | SN74HC1G04 | SN74HC1G04 | SN74HC1G04 | 0.1 | 0.1 | 0.1 | 0.1 | 0.1 | 0.1 | 0.1 | 0.1 | 110k | 110k | 110k | 110k | 0.01 | 0.01 | 0.01 | 0.01 | 0.1 | 0.1 | 0.1 | 0.1 | 0.1 | 0.1 | 0.1 | 0.1 | 0.1 | 0.1 | 0.1 | 0.1 | 0.1 | 0.1 | 0.1 | 0.1 | 0.1 | FOX924B | FOX924B | FOX924B | FOX924B | 0.1 | 0.1 | 0.1 | 0.1 | 0.1 | 0.1 | 0.1 | TPS77833D | TPS77833D | TPS77833D | 15 | 15 | 15 | 15 | 0.1 | 0.1 | 0.1 | 1 | 1 | 1 | 0.1 | TPS77833D | 1 | 300 | 300 | 300 | 2N3906B | 2N3906B | 2N3906B | 30k | 30k | 30k | 300 | 30k | 2N3906B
